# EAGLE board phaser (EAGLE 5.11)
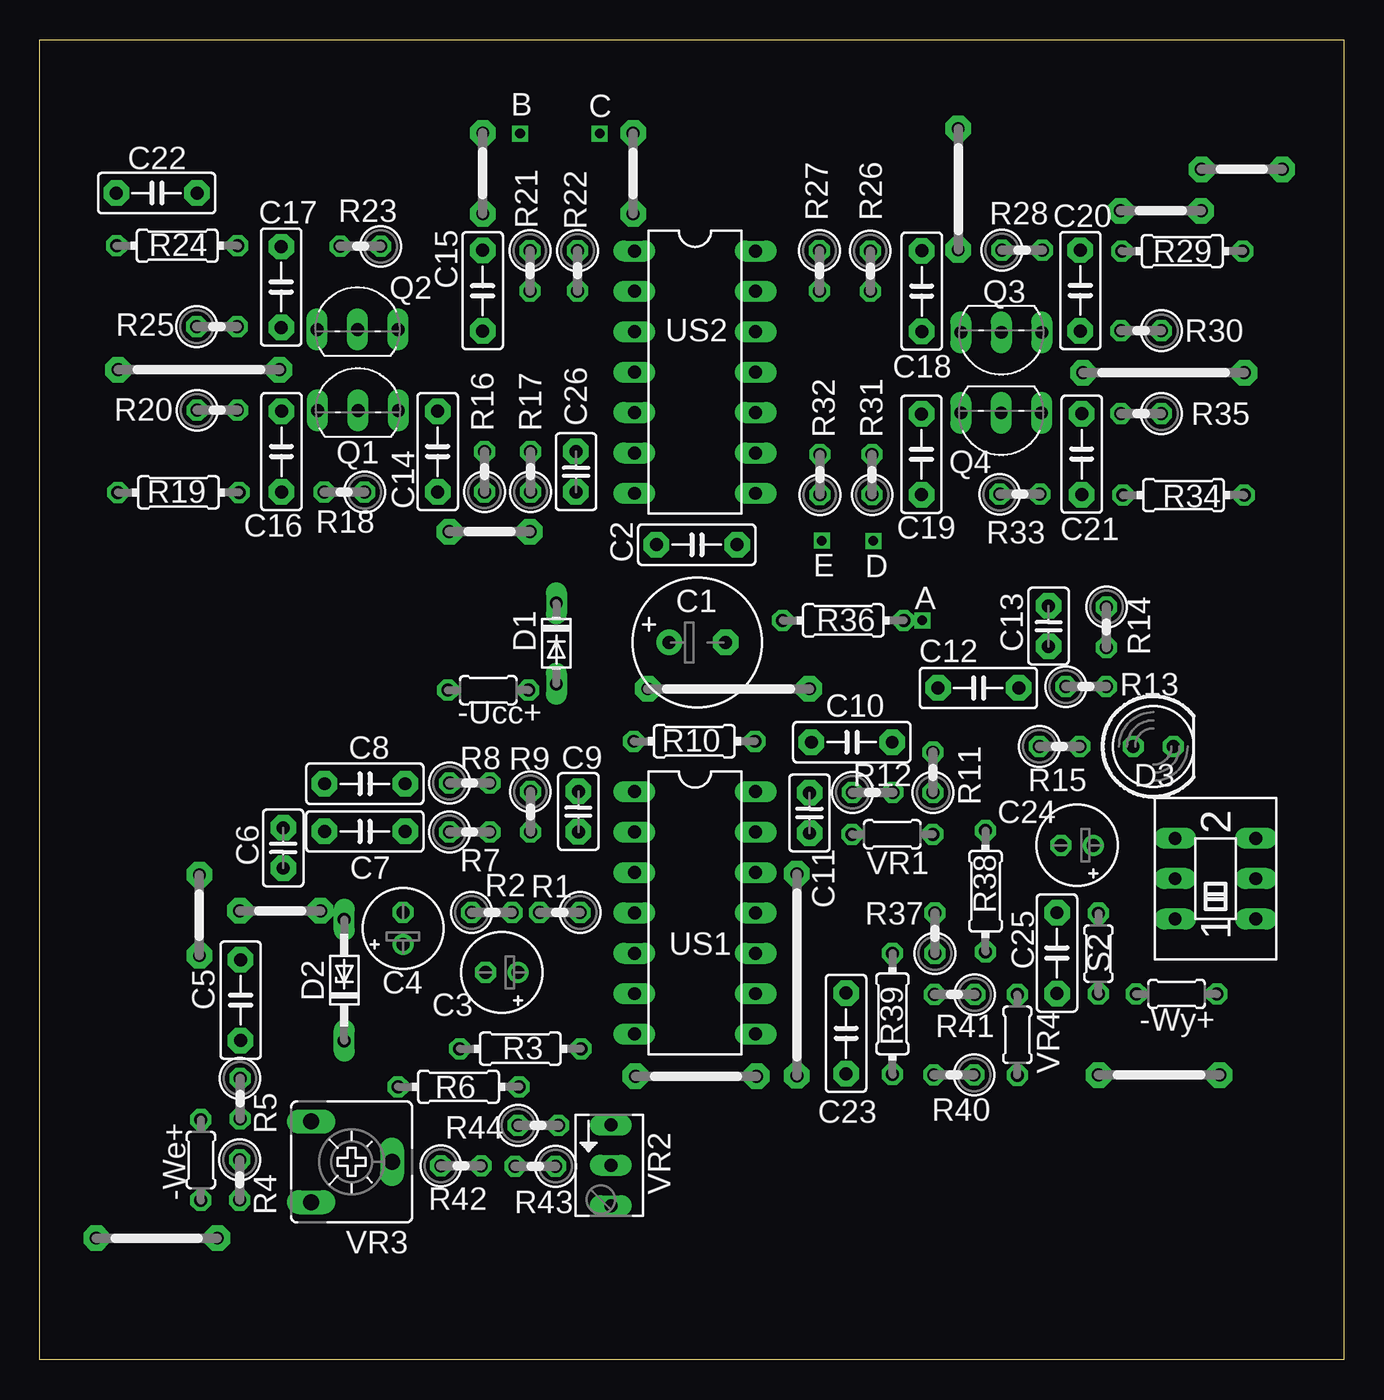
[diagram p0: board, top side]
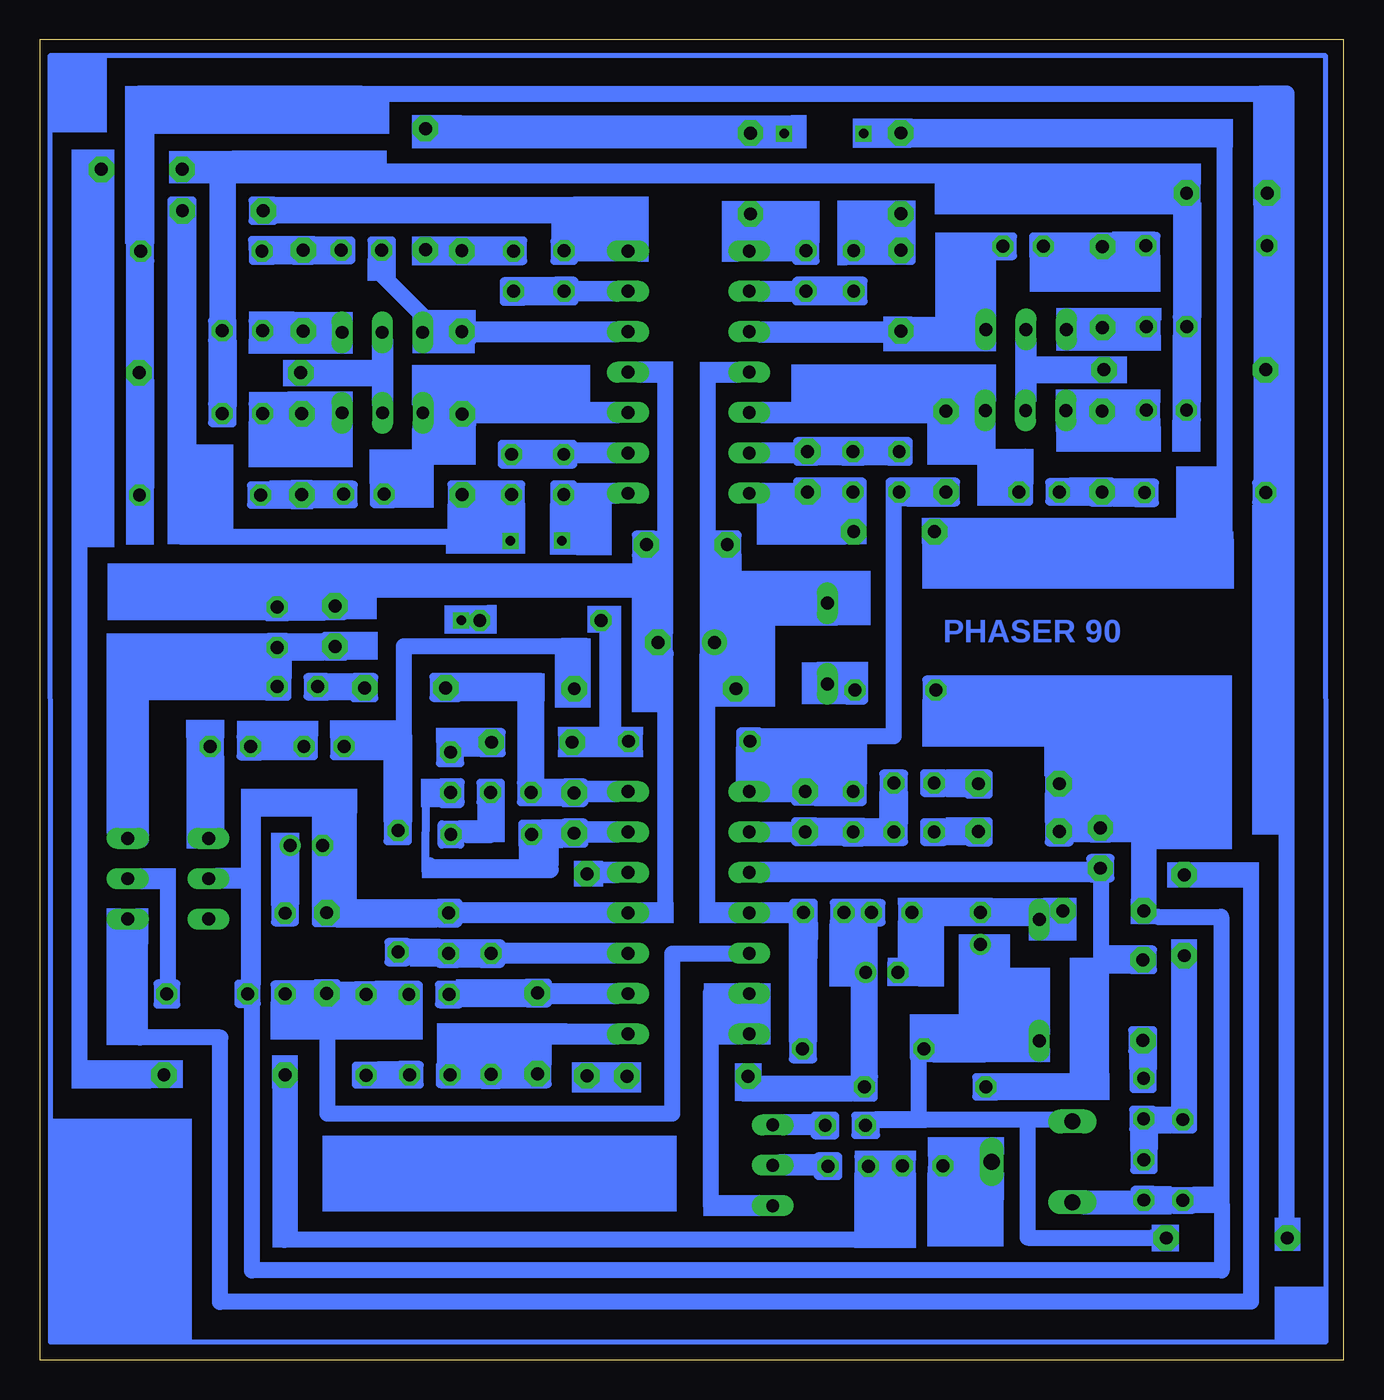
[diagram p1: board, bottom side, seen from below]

Size 82 x 83 mm. Coordinates in mm from the lower left corner, seen from the top.
Outline: 0,83 82,83 82,0 0,0 0,83
Copper layers (1*16): Top 0.035mm / dielectric 1.5mm / Bottom 0.035mm
Design rules "default": minimum track width 10mil, minimum drill 24mil, track to track 8mil, track to pad 8mil, pad to pad 8mil, via to via 8mil, smd to smd 8mil, copper to edge 40mil, drill to drill 8mil, minimum pad ring 10mil, minimum via ring 8mil, stop-mask expansion 4mil, vias tented up to drill 0mil, thermal gap 10mil

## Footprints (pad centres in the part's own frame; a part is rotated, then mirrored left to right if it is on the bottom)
DIL14 = drill 0.813 long: 1 -7.62,-3.81; 2 -5.08,-3.81; 3 -2.54,-3.81; 4 0,-3.81; 5 2.54,-3.81; 6 5.08,-3.81; 7 7.62,-3.81; 8 7.62,3.81; 9 5.08,3.81; 10 2.54,3.81; 11 0,3.81; 12 -2.54,3.81; 13 -5.08,3.81; 14 -7.62,3.81
C2.5-2 = drill 0.813 pad 1.6 octagon: 1 -1.27,0; 2 1.27,0
C5B2.5 = drill 0.813 pad 1.6 octagon: 1 -2.54,0; 2 2.54,0
0207/2V = drill 0.813 octagon: 1 -1.27,0; 2 1.27,0
0204/7 = drill 0.813 octagon: 1 -3.81,0; 2 3.81,0
DO34-5 = drill 0.813 long: A 2.54,0; C -2.54,0
DO34Z7 = drill 0.813 long: A 3.81,0; C -3.81,0
LED5MM = drill 0.813 octagon: A -1.27,0; K 1.27,0
0204/5 = drill 0.813 octagon: 1 -2.54,0; 2 2.54,0
07 = drill 0.813 pad 1.6 octagon: 1 -3.81,0; 2 3.81,0
TO92- = drill 0.813 long: 1 2.54,0; 2 0,0; 3 -2.54,0
05 = drill 0.813 pad 1.6 octagon: 1 -2.54,0; 2 2.54,0
10 = drill 0.813 pad 1.6 octagon: 1 -5.08,0; 2 5.08,0
E3,5-8 = drill 0.813 pad 1.6 round: + -1.778,0 | drill 0.813 pad 1.6 octagon: - 1.778,0
E2-5 = drill 0.813 pad 1.27 round: + -1.016,0 | drill 0.813 pad 1.27 octagon: - 1.016,0
12 = drill 0.813 pad 1.6 octagon: 1 -6.35,0; 2 6.35,0
CA6V = drill 1.016 long: A -2.54,-2.54; E 2.54,-2.54; S 0,2.54
B64Y = drill 0.813 long: A 2.54,0; E -2.54,0; S 0,0
A68-A31 = drill 0.813 long: 1 -2.54,-2.54; 2 0,-2.54; 3 2.54,-2.54; 4 -2.54,2.54; 5 0,2.54; 6 2.54,2.54

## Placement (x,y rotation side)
E$1  [DIL14]  41.2,62.1 270 top
E$2  [DIL14]  41.2,28.1 270 top
E$3  [C2.5-2]  33.72,55.84 90 top
E$4  [C5B2.5]  55.46,67.19 90 top
E$5  [0207/2V]  56.17,36.93 90 top
E$6  [0204/7]  50.52,46.49 0 top
E$7  [0207/2V]  49.02,68.47 270 top
E$8  [DO34-5]  32.48,45.04 270 top
E$9  [DO34Z7]  19.15,23.87 90 top
E$10  [LED5MM]  70.02,38.56 0 top
E$15  [0207/2V]  49.05,55.66 90 top
E$20  [0207/2V]  52.34,55.66 90 top
E$25  [0207/2V]  52.22,68.45 270 top
E$30  [0207/2V]  69.25,64.7 180 top
E$35  [0207/2V]  61.63,54.42 0 top
E$40  [0207/2V]  69.25,59.5 180 top
E$45  [0207/2V]  61.77,69.77 0 top
E$47  [C5B2.5]  50.7,20.52 90 top
E$52  [C5B2.5]  63.96,25.57 90 top
E$53  [0204/5]  28.2,42.1 0 top
E$54  [0204/7]  59.47,29.46 90 top
E$57  [C5B2.5]  59.02,42.24 0 top
E$58  [0204/5]  71.48,23 180 top
E$61  [C2.5-2]  48.4,34.38 90 top
E$62  [C5B2.5]  51.06,38.83 0 top
E$63  [0204/5]  66.57,25.54 90 top
E$64  [0204/7]  53.62,21.75 90 top
E$65  [0207/2V]  64.12,38.57 0 top
E$67  [C5B2.5]  12.63,22.61 90 top
E$68  [0204/5]  53.61,33.04 0 top
E$69  [0204/7]  26.33,17.16 0 top
E$70  [0207/2V]  31.16,12.17 180 top
E$71  [C2.5-2]  63.43,46.13 90 top
E$72  [C5B2.5]  20.44,36.22 0 top
E$73  [07]  7.36,7.65 0 top
E$74  [0204/7]  30.22,19.56 0 top
E$75  [0207/2V]  30.85,34.45 270 top
E$76  [C2.5-2]  15.31,32.18 270 top
E$77  [C5B2.5]  20.44,33.22 0 top
E$78  [0204/5]  61.47,20.43 90 top
E$79  [0204/7]  41.16,38.89 0 top
E$80  [0207/2V]  27.03,36.26 0 top
E$81  [C2.5-2]  33.87,34.47 90 top
E$82  [C5B2.5]  41.31,51.25 0 top
E$83  [0204/5]  10.13,12.56 270 top
E$84  [0204/7]  71.84,69.71 0 top
E$85  [0207/2V]  27.03,33.18 0 top
E$86  [TO92-]  60.45,59.54 180 top
E$87  [TO92-]  60.46,64.6 180 top
E$88  [TO92-]  20.01,59.69 0 top
E$89  [TO92-]  19.98,64.78 0 top
E$90  [0207/2V]  30.86,55.84 90 top
E$91  [0207/2V]  33.82,68.47 270 top
E$92  [0207/2V]  27.96,55.84 90 top
E$93  [0207/2V]  30.82,68.47 270 top
E$94  [0207/2V]  19.15,54.56 180 top
E$95  [0207/2V]  20.17,70.01 180 top
E$96  [0207/2V]  11.14,64.96 0 top
E$97  [0207/2V]  11.16,59.7 0 top
E$98  [C5B2.5]  25.02,57.1 90 top
E$99  [C5B2.5]  27.85,67.22 270 top
E$100  [C5B2.5]  15.18,67.45 90 top
E$101  [C5B2.5]  15.2,57.1 90 top
E$102  [C5B2.5]  7.35,73.36 0 top
E$103  [C5B2.5]  55.44,56.93 90 top
E$104  [C5B2.5]  65.43,67.23 90 top
E$105  [C5B2.5]  65.52,56.94 90 top
E$106  [0204/7]  8.64,70.05 0 top
E$107  [0204/7]  8.72,54.54 0 top
E$108  [0204/7]  71.92,54.37 0 top
E$109  [05]  10.04,27.95 90 top
E$110  [10]  10,62.25 0 top
E$111  [10]  70.67,62.06 0 top
E$112  [05]  37.31,74.59 90 top
E$113  [05]  70.49,72.25 180 top
E$114  [07]  57.75,73.6 90 top
E$115  [05]  27.86,74.6 90 top
E$116  [05]  28.28,52.07 0 top
E$117  [E3,5-8]  41.35,45.1 0 top
E$118  [0207/2V]  32.7,28.12 180 top
E$119  [0207/2V]  28.43,28.12 0 top
E$120  [0207/2V]  12.59,16.42 270 top
E$121  [0207/2V]  12.57,11.31 270 top
E$122  [0207/2V]  26.49,12.2 0 top
E$123  [E2-5]  22.84,27.12 90 top
E$124  [E2-5]  29.05,24.36 180 top
E$125  [05]  15.12,28.23 0 top
E$126  [07]  41.27,17.83 0 top
E$127  [12]  47.6,24.2 90 top
E$128  [CA6V]  19.61,12.44 270 top
E$129  [B64Y]  35.91,12.23 270 top
E$130  [0207/2V]  31.34,14.74 0 top
E$131  [0207/2V]  52.37,35.68 0 top
E$132  [0207/2V]  65.79,42.32 0 top
E$133  [0207/2V]  67.08,46.06 270 top
E$134  [0207/2V]  57.52,22.96 180 top
E$135  [E2-5]  65.23,32.35 180 top
E$136  [10]  43.31,42.19 0 top
E$137  [0207/2V]  56.29,26.82 90 top
E$138  [0207/2V]  57.48,17.92 180 top
E$139  [A68-A31]  73.93,30.25 90 top
E$140  [05]  75.59,74.86 180 top
E$141  [07]  70.38,17.9 0 top

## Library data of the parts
E$1 E$2 = analog-devices
E$3 E$4 E$47 E$52 E$57 E$61 E$62 E$67 E$71 E$72 E$76 E$77 E$81 E$82 E$98-E$105 = capacitor-wima
E$5-E$7 E$15 E$20 E$25 E$30 E$35 E$40 E$45 E$53 E$54 E$58 E$63-E$65 E$68-E$70 E$74 E$75 E$78-E$80 E$83-E$85 E$90-E$97 E$106-E$108 E$117-E$124 E$130-E$135 E$137 E$138 = rcl
E$8 E$9 = diode
E$10 = led
E$73 E$109-E$116 E$125-E$127 E$136 E$140 E$141 = jumper
E$86-E$89 = transistor-fet
E$128 E$129 = pot
E$139 = switch

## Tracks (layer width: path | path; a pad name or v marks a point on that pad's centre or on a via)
S$1
  Bottom 0.5: 33.09,53.92 33.09,55.23 34.36,55.23 34.36,53.93 33.12,53.93
S$2
  Bottom 0.5: 33.11,56.48 33.09,56.51 33.09,57.75 34.36,57.75 34.36,56.47 33.11,56.48
S$3
  Bottom 0.5: 54.82,64.01 54.82,65.3 56.14,65.3 56.14,64 54.85,63.99
S$4
  Bottom 0.5: 54.83,69.1 54.83,70.37 56.14,70.37 56.14,69.08 54.83,69.08
S$5
  Bottom 0.5: 55.53,35.1 55.53,36.33 56.75,36.3 56.75,34.96 55.54,34.96
S$6
  Bottom 0.5: 55.57,37.52 55.58,38.88 56.82,38.87 56.83,37.51 55.62,37.51
S$7
  Bottom 0.8: 46.39,39.12 46.42,39.12 46.42,45.64
S$8
  Bottom 1: 55.23,33 53.59,33 53.59,34.84
S$9
  Bottom 0.5: 49.63,70.33 49.63,69.1 48.41,69.1 48.41,70.39 49.62,70.39
S$10
  Bottom 0.5: 49.62,67.8 49.62,66.55 48.4,66.55 48.4,67.84 49.61,67.84
S$11
  Bottom 0.5: 68.14,39.16 69.37,39.16 69.37,37.94 68.09,37.94 68.09,39.13
S$12
  Bottom 0.5: 70.81,39.14 71.89,39.14 71.89,37.88 70.65,37.88 70.65,39.16 70.85,39.16
S$13
  Bottom 0.5: 57,35.56 57.72,35.56 57.73,30.83
S$14
  Bottom 1: 49.88,30.8 49.88,33.12
S$15
  Bottom 1: 49.89,30.78 57.49,30.78 57.49,31.09
S$21
  Bottom 0.5: 48.44,53.8 48.44,55.03 49.66,55.03 49.66,53.74 48.45,53.74
S$22
  Bottom 0.5: 48.45,56.33 48.45,57.58 49.67,57.58 49.67,56.29 48.46,56.29
S$31
  Bottom 0.5: 51.73,53.8 51.73,55.03 52.95,55.03 52.95,53.74 51.74,53.74
S$32
  Bottom 0.5: 51.74,56.33 51.74,57.58 52.96,57.58 52.96,56.29 51.75,56.29
S$41
  Bottom 0.5: 52.83,70.31 52.83,69.08 51.61,69.08 51.61,70.37 52.82,70.37
S$42
  Bottom 0.5: 52.82,67.78 52.82,66.53 51.6,66.53 51.6,67.82 52.81,67.82
S$51
  Bottom 0.5: 71.11,64.09 69.88,64.09 69.88,65.31 71.17,65.31 71.17,64.1
S$52
  Bottom 0.5: 68.58,64.1 67.33,64.1 67.33,65.32 68.62,65.32 68.62,64.11
S$61
  Bottom 0.5: 59.77,55.03 61,55.03 61,53.81 59.71,53.81 59.71,55.02
S$62
  Bottom 0.5: 62.3,55.02 63.55,55.02 63.55,53.8 62.26,53.8 62.26,55.01
S$71
  Bottom 0.5: 71.11,58.89 69.88,58.89 69.88,60.11 71.17,60.11 71.17,58.9
S$72
  Bottom 0.5: 68.58,58.9 67.33,58.9 67.33,60.12 68.62,60.12 68.62,58.91
S$81
  Bottom 0.5: 59.91,70.38 61.14,70.38 61.14,69.16 59.85,69.16 59.85,70.37
S$82
  Bottom 0.5: 62.44,70.37 63.69,70.37 63.69,69.15 62.4,69.15 62.4,70.36
S$85
  Bottom 0.5: 50.06,17.34 50.06,18.63 51.38,18.63 51.38,17.33 50.09,17.32
S$86
  Bottom 0.5: 50.07,22.43 50.07,23.7 51.38,23.7 51.38,22.41 50.07,22.41
S$95
  Bottom 0.5: 63.32,22.39 63.32,23.68 64.64,23.68 64.64,22.38 63.35,22.37
S$96
  Bottom 0.5: 63.33,27.48 63.33,28.75 64.64,28.75 64.64,27.46 63.33,27.46
S$97
  Bottom 0.5: 25.08,42.76 26.26,42.76 26.26,41.44 25.08,41.44 25.08,42.74
S$98
  Bottom 0.5: 30.16,42.72 31.32,42.72 31.32,41.46 30.16,41.46 30.16,42.68
S$99
  Bottom 0.5: 58.86,25.02 58.86,26.26 60.08,26.26 60.08,25 58.92,25
S$100
  Bottom 0.5: 58.84,32.69 58.84,33.88 60.14,33.88 60.14,32.61 58.86,32.61
S$105
  Bottom 0.5: 50.54,42.94 57.25,42.94 57.25,41.62 55.64,41.62 55.63,42.91
S$106
  Bottom 0.5: 60.99,42.92 62.26,42.92 62.26,41.61 60.97,41.61 60.97,42.92
S$107
  Bottom 0.5: 74.6,22.34 73.42,22.34 73.42,23.66 74.6,23.66 74.6,22.36
S$108
  Bottom 0.5: 69.52,22.38 68.36,22.38 68.36,23.64 69.52,23.64 69.52,22.42
S$113
  Bottom 0.5: 47.77,32.46 47.77,33.77 49.04,33.77 49.04,32.47 47.8,32.47
S$114
  Bottom 0.5: 47.79,35.02 47.77,35.05 47.77,36.29 49.04,36.29 49.04,35.01 47.79,35.02
S$115
  Bottom 0.5: 47.88,39.47 49.17,39.47 49.17,38.15 47.87,38.15 47.87,39.44
S$116
  Bottom 0.5: 52.97,39.46 54.24,39.46 54.24,38.15 52.95,38.15 52.95,39.46
S$117
  Bottom 0.5: 65.91,22.42 65.91,23.6 67.23,23.6 67.23,22.42 65.93,22.42
S$118
  Bottom 0.5: 65.95,27.5 65.95,28.66 67.21,28.66 67.21,27.5 65.99,27.5
S$119
  Bottom 0.5: 53.01,17.31 53.01,18.55 54.23,18.55 54.23,17.29 53.07,17.29
S$120
  Bottom 0.5: 52.99,24.98 52.99,26.17 54.29,26.17 54.29,24.9 53.01,24.9
S$121
  Bottom 0.5: 62.26,39.18 63.49,39.18 63.49,37.96 62.2,37.96 62.2,39.17
S$122
  Bottom 0.5: 64.79,39.17 66.04,39.17 66.04,37.95 64.75,37.95 64.75,39.16
S$125
  Bottom 0.5: 11.99,19.43 11.99,20.72 13.31,20.72 13.31,19.42 12.02,19.41
S$126
  Bottom 0.5: 12,24.52 12,25.79 13.31,25.79 13.31,24.5 12,24.5
S$127
  Bottom 0.5: 50.49,33.7 51.67,33.7 51.67,32.38 50.49,32.38 50.49,33.68
S$128
  Bottom 0.5: 55.57,33.66 56.73,33.66 56.73,32.4 55.57,32.4 55.57,33.62
S$129
  Bottom 0.5: 21.87,17.77 23.11,17.77 23.11,16.55 21.85,16.55 21.85,17.71
S$130
  Bottom 0.5: 29.54,17.79 30.75,17.79 30.75,16.49 29.56,16.47 29.56,17.75
S$131
  Bottom 0.5: 33.02,11.56 31.79,11.56 31.79,12.78 33.08,12.78 33.08,11.57
S$132
  Bottom 0.5: 30.49,11.57 29.24,11.57 29.24,12.79 30.53,12.79 30.53,11.58
S$133
  Bottom 0.5: 62.8,44.21 62.8,45.52 64.07,45.52 64.07,44.22 62.83,44.22
S$134
  Bottom 0.5: 62.82,46.77 62.8,46.8 62.8,48.04 64.07,48.04 64.07,46.76 62.82,46.77
S$135
  Bottom 0.5: 17.26,36.86 18.55,36.86 18.55,35.54 17.25,35.54 17.24,36.83
S$136
  Bottom 0.5: 22.35,36.85 23.62,36.85 23.62,35.54 22.33,35.54 22.33,36.85
S$137
  Bottom 1: 67.81,42.33 75.64,42.33 75.64,32.69
S$138
  Bottom 1: 7.68,9.81 7.68,5.61 68.65,5.61 68.65,22.16
S$139
  Bottom 0.5: 25.78,20.17 27.02,20.17 27.02,18.95 25.76,18.95 25.76,20.11
S$140
  Bottom 0.5: 33.45,20.19 34.64,20.19 34.64,18.89 33.37,18.89 33.37,20.17
S$141
  Bottom 0.5: 31.46,36.31 31.46,35.08 30.24,35.08 30.24,36.37 31.45,36.37
S$142
  Bottom 0.5: 31.45,33.78 31.45,32.53 30.23,32.53 30.23,33.82 31.44,33.82
S$143
  Bottom 0.5: 15.94,34.1 15.94,32.79 14.67,32.79 14.67,34.09 15.91,34.09
S$144
  Bottom 0.5: 15.92,31.54 15.94,31.51 15.94,30.27 14.67,30.27 14.67,31.55 15.92,31.54
S$145
  Bottom 0.5: 17.26,33.86 18.55,33.86 18.55,32.54 17.25,32.54 17.24,33.83
S$146
  Bottom 0.5: 22.35,33.85 23.62,33.85 23.62,32.54 22.33,32.54 22.33,33.85
S$147
  Bottom 0.5: 60.81,17.31 60.81,18.49 62.13,18.49 62.13,17.31 60.83,17.31
S$148
  Bottom 0.5: 60.85,22.39 60.85,23.55 62.11,23.55 62.11,22.39 60.89,22.39
S$149
  Bottom 0.5: 36.72,39.5 37.96,39.5 37.96,38.28 36.7,38.28 36.7,39.44
S$150
  Bottom 0.5: 44.39,39.52 45.58,39.52 45.58,38.22 44.31,38.22 44.31,39.5
S$151
  Bottom 0.5: 25.17,36.87 26.4,36.87 26.4,35.65 25.11,35.65 25.11,36.86
S$152
  Bottom 0.5: 27.7,36.86 28.95,36.86 28.95,35.64 27.66,35.64 27.66,36.85
S$153
  Bottom 0.5: 33.24,32.55 33.24,33.86 34.51,33.86 34.51,32.56 33.27,32.56
S$154
  Bottom 0.5: 33.26,35.11 33.24,35.14 33.24,36.38 34.51,36.38 34.51,35.1 33.26,35.11
S$155
  Bottom 0.5: 38.13,51.9 39.42,51.9 39.42,50.59 38.12,50.59 38.12,51.85
S$156
  Bottom 0.5: 43.34,51.88 44.51,51.88 44.51,50.59 43.18,50.59 43.18,51.88
S$157
  Bottom 0.5: 10.79,15.68 10.79,14.5 9.47,14.5 9.47,15.68 10.77,15.68
S$158
  Bottom 0.5: 10.75,10.6 10.75,9.44 9.49,9.44 9.49,10.6 10.71,10.6
S$159
  Bottom 0.5: 67.41,70.4 68.65,70.4 68.61,69.1 67.35,69.1 67.35,70.39
S$160
  Bottom 0.5: 75.04,70.33 76.34,70.33 76.34,69.08 75.04,69.08 75.04,70.34
S$161
  Bottom 0.5: 25.17,33.79 26.4,33.79 26.4,32.57 25.11,32.57 25.11,33.78
S$162
  Bottom 0.5: 27.7,33.78 28.95,33.78 28.95,32.56 27.66,32.56 27.66,33.77
S$163
  Bottom 0.5: 30.25,53.98 30.25,55.21 31.47,55.21 31.47,53.92 30.26,53.92
S$164
  Bottom 0.5: 30.26,56.51 30.26,57.76 31.48,57.76 31.48,56.47 30.27,56.47
S$165
  Bottom 0.5: 34.43,70.33 34.43,69.1 33.21,69.1 33.21,70.39 34.42,70.39
S$166
  Bottom 0.5: 34.42,67.8 34.42,66.55 33.2,66.55 33.2,67.84 34.41,67.84
S$167
  Bottom 0.5: 27.35,53.98 27.35,55.21 28.57,55.21 28.57,53.92 27.36,53.92
S$168
  Bottom 0.5: 27.36,56.51 27.36,57.76 28.58,57.76 28.58,56.47 27.37,56.47
S$169
  Bottom 0.5: 31.43,70.33 31.43,69.1 30.21,69.1 30.21,70.39 31.42,70.39
S$170
  Bottom 0.5: 31.42,67.8 31.42,66.55 30.2,66.55 30.2,67.84 31.41,67.84
S$171
  Bottom 0.5: 21.01,53.95 19.78,53.95 19.78,55.17 21.07,55.17 21.07,53.96
S$172
  Bottom 0.5: 18.48,53.96 17.23,53.96 17.23,55.18 18.52,55.18 18.52,53.97
S$173
  Bottom 0.5: 22.03,69.4 20.8,69.4 20.8,70.62 22.09,70.62 22.09,69.41
S$174
  Bottom 0.5: 19.5,69.41 18.25,69.41 18.25,70.63 19.54,70.63 19.54,69.42
S$175
  Bottom 0.5: 9.28,65.57 10.51,65.57 10.51,64.35 9.22,64.35 9.22,65.56
S$176
  Bottom 0.5: 11.81,65.56 13.06,65.56 13.06,64.34 11.77,64.34 11.77,65.55
S$177
  Bottom 0.5: 9.3,60.31 10.53,60.31 10.53,59.09 9.24,59.09 9.24,60.3
S$178
  Bottom 0.5: 11.83,60.3 13.08,60.3 13.08,59.08 11.79,59.08 11.79,60.29
S$179
  Bottom 0.5: 24.38,53.92 24.38,55.21 25.7,55.21 25.7,53.91 24.41,53.9
S$180
  Bottom 0.5: 24.39,59.01 24.39,60.28 25.7,60.28 25.7,58.99 24.39,58.99
S$181
  Bottom 0.5: 28.49,70.4 28.49,69.11 27.17,69.11 27.17,70.4 28.49,70.4
S$182
  Bottom 0.5: 28.48,65.31 28.48,64.04 27.17,64.04 27.17,65.33 28.48,65.33
S$183
  Bottom 0.5: 14.54,64.27 14.54,65.56 15.86,65.56 15.86,64.26 14.57,64.25
S$184
  Bottom 0.5: 14.55,69.36 14.55,70.63 15.86,70.63 15.86,69.34 14.55,69.34
S$185
  Bottom 0.5: 14.56,53.92 14.56,55.21 15.88,55.21 15.88,53.91 14.59,53.9
S$186
  Bottom 0.5: 14.57,59.01 14.57,60.28 15.88,60.28 15.88,58.99 14.57,58.99
S$187
  Bottom 0.5: 4.17,74 5.46,74 5.46,72.68 4.16,72.68 4.15,73.97
S$188
  Bottom 0.5: 9.26,73.99 10.53,73.99 10.53,72.68 9.24,72.68 9.24,73.99
S$189
  Bottom 0.5: 54.8,53.75 54.8,55.04 56.12,55.04 56.12,53.74 54.83,53.73
S$190
  Bottom 0.5: 54.81,58.84 54.81,60.11 56.12,60.11 56.12,58.82 54.81,58.82
S$191
  Bottom 0.5: 64.79,64.05 64.79,65.34 66.11,65.34 66.11,64.04 64.82,64.03
S$192
  Bottom 0.5: 64.8,69.14 64.8,70.41 66.11,70.41 66.11,69.12 64.8,69.12
S$193
  Bottom 0.5: 64.88,53.76 64.88,55.05 66.2,55.05 66.2,53.75 64.91,53.74
S$194
  Bottom 0.5: 64.89,58.85 64.89,60.12 66.2,60.12 66.2,58.83 64.89,58.83
S$195
  Bottom 0.5: 4.2,70.66 5.44,70.66 5.44,69.44 4.18,69.44 4.18,70.6
S$196
  Bottom 0.5: 11.87,70.68 13.06,70.68 13.06,69.38 11.79,69.38 11.79,70.66
S$197
  Bottom 0.5: 4.28,55.15 5.52,55.15 5.52,53.93 4.26,53.93 4.26,55.09
S$198
  Bottom 0.5: 11.95,55.17 13.14,55.17 13.14,53.87 11.87,53.87 11.87,55.15
S$199
  Bottom 0.5: 67.48,54.98 68.72,54.98 68.72,53.76 67.46,53.76 67.46,54.92
S$200
  Bottom 0.5: 75.15,55 76.34,55 76.34,53.7 75.07,53.7 75.07,54.98
S$201
  Bottom 1: 58,65.73 60.45,68.18 60.45,68.94
S$202
  Bottom 1: 4.75,74.39 4.75,79.59 62.1,79.59
S$203
  Bottom 1: 61.83,79.61 75.73,79.61 75.73,70.68
S$204
  Bottom 1: 20.03,56.78 22.42,56.77 22.41,58.78
S$205
  Bottom 1: 24.81,52.1 7.5,52.1 7.5,77.17 26.89,77.17
S$206
  Bottom 1: 73.09,71.2 73.09,51.76 55.44,51.76 55.44,53.46 55.52,53.46
S$207
  Bottom 0.5: 72.41,72.9 72.41,71.57 73.7,71.57 73.71,72.9 72.41,72.9 | 72.41,72.9 72.4,72.9
S$208
  Bottom 0.5: 67.4,72.89 68.62,72.89 68.62,71.61 67.29,71.61 67.31,72.91
S$209
  Bottom 0.5: 38.14,76.42 36.58,76.42 36.58,77.98 38.18,77.98 38.18,76.43
S$210
  Bottom 0.5: 27.2,77.79 28.53,77.79 28.53,76.47 27.21,76.47 27.21,77.78
S$211
  Bottom 0.5: 38.95,45.72 38.94,45.73 | 38.94,45.73 40.26,45.73 40.26,44.44 38.94,44.44 38.94,45.73
S$212
  Bottom 0.5: 42.43,45.75 43.79,45.74 43.79,44.43 42.43,44.44 42.43,45.75
S$213
  Bottom 1: 38.34,62.11 40.01,62.11 40,45.87
S$214
  Bottom 1: 44.04,62.16 42.68,62.16 42.68,45.96
S$215
  Bottom 1: 38.45,28.09 40.02,28.09 40.02,44.27
S$216
  Bottom 1: 44.04,28.09 42.65,28.09 42.65,44.39
S$217
  Bottom 1: 75.16,17.82 79.5,17.82 79.5,75.19
S$218
  Bottom 0.5: 34.56,27.51 33.33,27.51 33.33,28.73 34.62,28.73 34.62,27.52
S$219
  Bottom 0.5: 32.03,27.52 30.78,27.52 30.78,28.74 32.07,28.74 32.07,27.53
S$220
  Bottom 0.5: 26.57,28.73 27.8,28.73 27.8,27.51 26.51,27.51 26.51,28.72
S$221
  Bottom 0.5: 29.1,28.72 30.35,28.72 30.35,27.5 29.06,27.5 29.06,28.71
S$222
  Bottom 0.5: 12.02,15.72 13.25,15.72 13.25,14.5 11.96,14.5 11.96,15.71
S$223
  Bottom 0.5: 12.01,17.07 12.01,18.32 13.23,18.32 13.23,17.03 12.02,17.03
S$224
  Bottom 0.5: 13.18,13.17 13.18,11.94 11.96,11.94 11.96,13.23 13.17,13.23
S$225
  Bottom 0.5: 13.17,10.64 13.17,9.39 11.95,9.39 11.95,10.68 13.16,10.68
S$226
  Bottom 0.5: 24.68,12.87 25.91,12.87 25.93,11.49 24.64,11.49 24.62,12.83
S$227
  Bottom 0.5: 27.21,12.87 28.46,12.87 28.46,11.51 27.17,11.51 27.17,12.85
S$228
  Bottom 1: 36.58,39.21 28.3,39.22 28.3,53.76
S$229
  Bottom 1: 21.59,17.23 15.26,17.23 15.26,29.98
S$230
  Bottom 1: 13.65,25.08 15.13,25.08 15.13,25.12
S$231
  Bottom 1: 11.72,27.86 7.72,27.86 7.72,9.78 9.13,9.78
S$232
  Bottom 1: 18.13,15.07 26.73,15.07 26.73,18.68
S$233
  Bottom 0.5: 29.48,15.35 30.71,15.35 30.71,14.13 29.42,14.13 29.42,15.34
S$234
  Bottom 0.5: 32.01,15.34 33.26,15.34 33.26,14.12 31.97,14.12 31.97,15.33
S$235
  Bottom 1: 36.8,9.62 39.78,9.62 39.78,23.15
S$236
  Bottom 1: 38.34,25.52 42.24,25.52 42.24,15.52
S$237
  Bottom 0.5: 50.51,36.29 51.74,36.29 51.74,35.07 50.45,35.07 50.45,36.28
S$238
  Bottom 0.5: 53.04,36.28 54.29,36.28 54.29,35.06 53,35.06 53,36.27
S$239
  Bottom 0.5: 63.93,42.93 65.16,42.93 65.16,41.71 63.87,41.71 63.87,42.92
S$240
  Bottom 0.5: 66.46,42.92 67.71,42.92 67.71,41.7 66.42,41.7 66.42,42.91
S$241
  Bottom 0.5: 67.69,47.92 67.69,46.69 66.47,46.69 66.47,47.98 67.68,47.98
S$242
  Bottom 0.5: 67.68,45.39 67.68,44.14 66.46,44.14 66.46,45.43 67.67,45.43
S$243
  Bottom 0.5: 59.38,22.35 58.15,22.35 58.15,23.57 59.44,23.57 59.44,22.36
S$244
  Bottom 0.5: 56.85,22.36 55.6,22.36 55.6,23.58 56.89,23.58 56.89,22.37
S$245  (via drill 0.6)
  other vias: 55.5,46.49
S$246
  Bottom 1: 48.44,43.11 48.44,44.85 59.12,44.85 59.12,34.13
S$247
  Bottom 1: 45.91,28.12 55.38,28.12
S$248
  Bottom 0.5: 55.68,24.96 55.68,26.19 56.9,26.19 56.9,24.9 55.69,24.9
S$249
  Bottom 0.5: 55.69,27.49 55.69,28.74 56.91,28.74 56.91,27.45 55.7,27.45
S$250
  Bottom 0.5: 59.34,17.31 58.11,17.31 58.11,18.53 59.4,18.53 59.4,17.32
S$251
  Bottom 0.5: 56.81,17.32 55.56,17.32 55.56,18.54 56.85,18.54 56.85,17.33
S$252
  Bottom 1: 63.92,22.09 63.92,15.49 42.22,15.49
S$253
  Bottom 1: 68.82,34.64 64.05,34.63 64.05,33.19
S$254
  Bottom 1: 70.47,30.27 68.83,30.27 68.83,34.63
S$255
  Bottom 1: 75.53,30.27 73.95,30.27 73.95,23.92
S$256
  Bottom 1: 5.85,30.49 5.85,3.65 70.67,3.63 70.67,20.2
S$257
  Bottom 1: 70.65,20.26 75.69,20.26 75.69,27.72
S$258
  Bottom 1: 19.88,15.03 19.88,7.67 12.06,7.67
S$259
  Bottom 1: 9.11,30.52 5.92,30.52
S$260
  Bottom 1: 28.81,11.05 28.81,7.53 66.63,7.53 66.64,16.92
S$261
  Bottom 1: 3.59,8.78 3.59,79.61 5.2,79.61
S$262
  Bottom 0.3: 1.15,1.11 81.31,1.11 81.33,82.02 1.17,82.02 1.15,1.11
S$263  (via drill 0.6)
  other vias: 49.17,51.5
S$264  (via drill 0.6)
  other vias: 30.2,77.1
S$265  (via drill 0.6)
  other vias: 35.2,77.1
S$266  (via drill 0.6)
  other vias: 52.41,51.49
(copper drawn outside any net)
  shapes: Bottom area x448

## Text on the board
Bottom: PHASER 90
tNames: B | C | C22 | R27 | R26 | R23 | R24 | C17 | C15 | R21 | R22 | R28 | C20 | R29 | Q3 | Q2 | R25 | US2 | R30 | R16 | R17 | C26 | C18 | R35 | R20 | Q1 | R32 | R31 | C14 | Q4 | R34 | R19 | C16 | R33 | C21 | R18 | C19 | E | D | C2 | A | C1 | R36 | D1 | C12 | C13 | R14 | R13 | -Ucc+ | C10 | C8 | R8 | R10 | R9 | C9 | R15 | R12 | D3 | R11 | C24 | C7 | R7 | C11 | VR1 | R38 | C6 | R2 | R1 | R37 | C25 | D2 | US1 | C4 | S2 | C5 | C3 | R41 | -Wy+ | R39 | R3 | R6 | VR4 | R40 | R44 | C23 | R5 | VR2 | R42 | R43 | -We+ | R4 | VR3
